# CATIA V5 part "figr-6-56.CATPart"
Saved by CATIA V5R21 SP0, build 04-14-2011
Part number: Part1
Bounding box of the stored display mesh (mm): x -50.648 to 50.648, y -72.183 to 72.183, z -40 to 40
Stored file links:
  D:\CATIA V5R21 E-RESOURCES\CATIA-V5R21\catia-v5r21-prt\c06-catia-v5r21-prt\c06-catia-v5r21-figr-6-56.CATPart
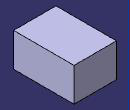
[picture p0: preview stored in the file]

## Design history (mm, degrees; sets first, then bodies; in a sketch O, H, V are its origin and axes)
Body1 (main body)
  Sketch1 on xy-plane, origin (0, 0, 0), H (1, 0, 0), V (0, 1, 0)
    line L1 (-50.6478, 72.1832) -> (50.6478, 72.1832)
    line L2 (50.6478, 72.1832) -> (50.6478, -72.1832)
    line L3 (50.6478, -72.1832) -> (-50.6478, -72.1832)
    line L4 (-50.6478, -72.1832) -> (-50.6478, 72.1832)
    axis line L5 (50.6478, -72.1832) -> (-50.6478, 72.1832)
    horizontal: L1 H, L3 H
    vertical: L2 V, L4 V
    midpoint: O L5
  Pad1: profile Sketch1, direction (0, 0, 1), length 40, mirrored extent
